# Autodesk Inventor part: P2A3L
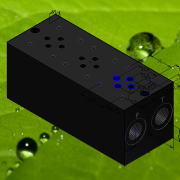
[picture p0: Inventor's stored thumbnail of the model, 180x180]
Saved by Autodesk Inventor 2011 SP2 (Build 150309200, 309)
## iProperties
Created: 2010-08
Part Number: P2A3L
Material: По умолчанию
Document SubType Name: Modeling
Designer: tananaev
Density: 1 g/cm^3
Author: tananaev
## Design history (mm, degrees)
derived "P2A2-8L.ipt" dims "d3" = 0, "d4" = 6, "d5" = 5.5, "d7" = 11, "d8" = 11.5, "d11" = 118 deg, "d14" = 158, "d15" = 19.5, "d16" = 14.75, "d17" = 31, "d18" = 32.5, "d21" = 18.75, "d22" = 40.5, "d23" = 7.5, "d24" = 21.5, "d25" = 30.2, "d26" = 12.7, "d27" = 15.5, "d28" = 25.9, "d29" = 5.1, "d31" = 0, "d34" = 5.5, "d36" = 90 deg, "d37" = 11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
node "Твердое тело1"
feature "Твердое тело1::P2A2-8L.ipt" dims "d2" = 70, "d3" = 0, "d4" = 6, "d5" = 5.5, "d7" = 11, "d8" = 11.5, "d10" = 40, "d11" = 118 deg, "d12" = 20, "d14" = 158, "d15" = 19.5, "d16" = 14.75, "d17" = 31, "d18" = 32.5, "d21" = 18.75, "d22" = 40.5, "d23" = 7.5, "d24" = 21.5, "d25" = 30.2, "d26" = 12.7, "d27" = 15.5, "d28" = 25.9, "d29" = 5.1, "d30" = 30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
tag "Элемент создания маркировки1"
